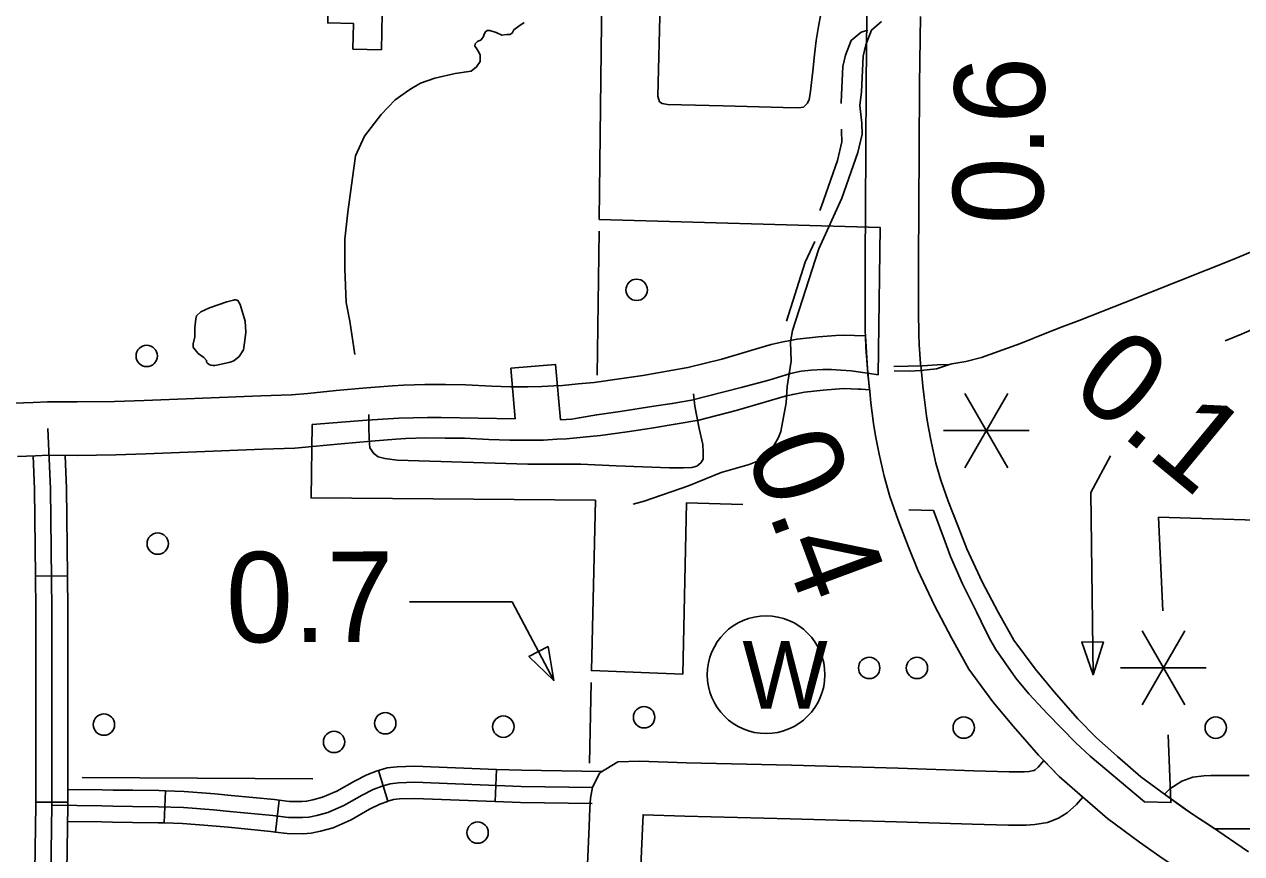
# Model space of a CAD drawing. Extents: x 1382482 to 1385815, y 1168351 to 1170484.
# Drawn here: x 1384167.8 to 1384395.6, y 1168843.1 to 1168998.2 of the extents above; entities that cross this region are included whole.
import ezdxf

# ---------------------------------------------------------------- set-up
doc = ezdxf.new("R2010")
doc.units = 0
for name, color, linetype in [('10', 7, 'Continuous'), ('15', 7, 'Continuous'), ('32', 7, 'Continuous'), ('35', 7, 'Continuous'), ('43', 7, 'Continuous'), ('48', 7, 'Continuous'), ('5', 7, 'Continuous'), ('57', 7, 'Continuous'), ('6', 7, 'Continuous'), ('Default', 7, 'Continuous')]:
    doc.layers.add(name, color=color, linetype=linetype)

msp = doc.modelspace()

# ---------------------------------------------------------------- linework, layer by layer
at = {"layer": '10'}
for points in [[(1384165.85, 1168927.3), (1384169.46, 1168927.46), (1384172.14, 1168927.6), (1384177.69, 1168927.55), (1384184.68, 1168927.65), (1384190.21, 1168927.83), (1384199.63, 1168928.21), (1384212.07, 1168928.69), (1384217.83, 1168928.9), (1384220.83, 1168929.15), (1384226.17, 1168929.68), (1384231.85, 1168930.18), (1384236.67, 1168930.58), (1384238.73, 1168930.69), (1384242.74, 1168930.83), (1384246.62, 1168930.8), (1384250.44, 1168930.77), (1384255.21, 1168930.52), (1384258.83, 1168930.37), (1384262.01, 1168930.4), (1384264.62, 1168930.42), (1384266.88, 1168930.54), (1384268.5, 1168930.64), (1384271.43, 1168930.91), (1384274.42, 1168931.21), (1384279.17, 1168931.85), (1384283.52, 1168932.52), (1384291.96, 1168933.96), (1384298.3, 1168935.56), (1384303.74, 1168937.19), (1384307.55, 1168938.27), (1384309.45, 1168938.75), (1384312.37, 1168939.29), (1384316.38, 1168939.71), (1384319.62, 1168939.95), (1384321.06, 1168940.05), (1384325.16, 1168939.9), (1384325.53, 1168933.74), (1384325.95, 1168929.84)], [(1384325.95, 1168929.84), (1384324.34, 1168929.92), (1384323.81, 1168929.94), (1384321.22, 1168930.04), (1384320.34, 1168929.98), (1384317.28, 1168929.75), (1384313.79, 1168929.38), (1384311.57, 1168928.97), (1384310.13, 1168928.61), (1384306.54, 1168927.59), (1384300.96, 1168925.92), (1384294.02, 1168924.17), (1384285.12, 1168922.65), (1384280.6, 1168921.96), (1384275.59, 1168921.28), (1384272.39, 1168920.96), (1384269.26, 1168920.67), (1384267.46, 1168920.56), (1384264.95, 1168920.42), (1384262.1, 1168920.4), (1384258.67, 1168920.37), (1384254.73, 1168920.53), (1384250.14, 1168920.78), (1384246.55, 1168920.8), (1384242.88, 1168920.83), (1384239.17, 1168920.7), (1384237.35, 1168920.6), (1384232.7, 1168920.22), (1384227.1, 1168919.72), (1384221.73, 1168919.2), (1384218.43, 1168918.92), (1384212.45, 1168918.69), (1384200.02, 1168918.22), (1384190.58, 1168917.84), (1384184.92, 1168917.65), (1384177.72, 1168917.55), (1384172.35, 1168917.6), (1384169.94, 1168917.47), (1384166.56, 1168917.32)], [(1384365.82, 1168853.64), (1384361.43, 1168857.53), (1384358.53, 1168860.52), (1384357.47, 1168859.25), (1384356.91, 1168858.76), (1384356.74, 1168858.65), (1384356.6, 1168858.6), (1384355.77, 1168858.47), (1384354.85, 1168858.4), (1384352.05, 1168858.4), (1384345.44, 1168858.59), (1384331.3, 1168859.04), (1384311.32, 1168859.6), (1384291.69, 1168860.08), (1384282.92, 1168860.37), (1384278.87, 1168860.22), (1384275.5, 1168858.19), (1384274.11, 1168855.53), (1384273.75, 1168853.47), (1384273.63, 1168851.61), (1384273.48, 1168848.22), (1384272.96, 1168836.83)], [(1384390.53, 1168847.69), (1384386.36, 1168850.44), (1384381.11, 1168854.22), (1384382.09, 1168855.22), (1384384.34, 1168856.66), (1384386.41, 1168857.37), (1384388.49, 1168857.65), (1384389.8, 1168857.69), (1384393.21, 1168857.69), (1384396.93, 1168857.69)], [(1384280.65, 1168783.46), (1384280.8, 1168787.57), (1384282.14, 1168814.84), (1384282.95, 1168836.41), (1384283.47, 1168847.78), (1384283.58, 1168850.34), (1384291.4, 1168850.08), (1384311.06, 1168849.6), (1384331, 1168849.04), (1384345.14, 1168848.6), (1384351.91, 1168848.4), (1384355.22, 1168848.4), (1384356.89, 1168848.53), (1384359.21, 1168848.88), (1384361.27, 1168849.69), (1384362.91, 1168850.72), (1384364.65, 1168852.24), (1384365.82, 1168853.64)], [(1384397.11, 1168847.69), (1384393.21, 1168847.69), (1384390.53, 1168847.69)]]:
    msp.add_lwpolyline(points, dxfattribs=at)
at = {"layer": '15'}
for points in [[(1384331.32, 1168905.43), (1384329.76, 1168909.85), (1384328.65, 1168913.64), (1384327.74, 1168917.81), (1384327.06, 1168921.21), (1384326.68, 1168923.5), (1384326.19, 1168927.36), (1384325.98, 1168929.52), (1384325.64, 1168932.77), (1384325.53, 1168933.74), (1384325.24, 1168937.76), (1384325.18, 1168939.82), (1384325.15, 1168940.73), (1384325.1, 1168943.59), (1384325.1, 1168953.72), (1384325.25, 1168974.6), (1384325.28, 1168987.04), (1384325.44, 1168999.69)], [(1384335.44, 1168999.6), (1384335.28, 1168986.96), (1384335.25, 1168974.55), (1384335.1, 1168953.69), (1384335.1, 1168943.67), (1384335.14, 1168940.99), (1384335.17, 1168940.16), (1384335.23, 1168938.27), (1384335.49, 1168934.67), (1384335.58, 1168933.87), (1384335.93, 1168930.53), (1384336.13, 1168928.47), (1384336.58, 1168924.96), (1384336.9, 1168923.01), (1384337.53, 1168919.85), (1384338.35, 1168916.11), (1384339.28, 1168912.92), (1384340.65, 1168909.02)], [(1384340.65, 1168909.02), (1384342.5, 1168904.23), (1384344.16, 1168900.06), (1384347.02, 1168893.93), (1384350.02, 1168888.23), (1384352.96, 1168883.01), (1384356.9, 1168877.63), (1384360.46, 1168873.35), (1384364.91, 1168868.3), (1384368.34, 1168864.77), (1384372.35, 1168861.22), (1384376.68, 1168857.47), (1384382.31, 1168853.34), (1384385, 1168851.42), (1384386.36, 1168850.44), (1384389.88, 1168848.14), (1384396.81, 1168843.43)], [(1384521.35, 1168747.9), (1384489.62, 1168768.93), (1384471.27, 1168781.28), (1384459.46, 1168789.26), (1384446.89, 1168797.82), (1384429.71, 1168809.31), (1384403.51, 1168826.99), (1384391.24, 1168835.12), (1384384.33, 1168839.82), (1384380.68, 1168842.21), (1384379.17, 1168843.3), (1384376.45, 1168845.24), (1384370.45, 1168849.65), (1384365.76, 1168853.69), (1384361.43, 1168857.53), (1384357.56, 1168861.51), (1384352.86, 1168866.85), (1384349.01, 1168871.47), (1384344.54, 1168877.59), (1384341.24, 1168883.44), (1384338.06, 1168889.49), (1384334.98, 1168896.09), (1384333.19, 1168900.58), (1384331.32, 1168905.43)]]:
    msp.add_lwpolyline(points, dxfattribs=at)
at = {"layer": '32'}
for p, q in [((1384255.89, 1168852.85), (1384256.12, 1168858.84)), ((1384235.83, 1168852.88), (1384234.09, 1168858.62)), ((1384193.97, 1168848.82), (1384194.2, 1168854.82)), ((1384214.78, 1168847.11), (1384215.48, 1168853.07))]:
    msp.add_line(p, q, dxfattribs=at)
for points in [[(1384234.09, 1168858.62), (1384235.67, 1168859.1), (1384237.57, 1168859.31), (1384240.84, 1168859.43), (1384256.12, 1168858.84)], [(1384256.12, 1168858.84), (1384260.83, 1168858.66), (1384275.86, 1168858.41)], [(1384215.48, 1168853.07), (1384217.4, 1168852.85), (1384219.78, 1168852.81), (1384220.63, 1168852.88), (1384221.81, 1168853.13), (1384223.62, 1168853.61), (1384226.26, 1168854.76), (1384229.57, 1168856.65), (1384231.9, 1168857.83), (1384233.84, 1168858.54), (1384234.09, 1168858.62)], [(1384172.97, 1168852.13), (1384182.31, 1168852.02), (1384184.35, 1168851.95), (1384188.07, 1168851.92), (1384192.93, 1168851.86), (1384197.59, 1168851.69), (1384203.22, 1168851.3), (1384206.24, 1168850.99), (1384214.28, 1168850.19), (1384217.21, 1168849.85), (1384219.87, 1168849.81), (1384221.06, 1168849.9), (1384222.51, 1168850.21), (1384224.61, 1168850.76), (1384227.61, 1168852.07), (1384231, 1168854.01), (1384233.1, 1168855.08), (1384234.79, 1168855.7), (1384236.27, 1168856.15), (1384237.79, 1168856.32), (1384240.83, 1168856.42), (1384260.75, 1168855.66), (1384274.09, 1168855.44)], [(1384175.97, 1168855.09), (1384182.37, 1168855.02), (1384184.42, 1168854.95), (1384188.1, 1168854.92), (1384193, 1168854.86), (1384194.2, 1168854.82)], [(1384194.2, 1168854.82), (1384197.75, 1168854.69), (1384203.47, 1168854.29), (1384206.54, 1168853.97), (1384214.6, 1168853.18), (1384215.48, 1168853.07)], [(1384214.78, 1168847.11), (1384217.01, 1168846.85), (1384219.96, 1168846.81), (1384221.48, 1168846.92), (1384223.2, 1168847.29), (1384225.6, 1168847.92), (1384228.96, 1168849.39), (1384232.42, 1168851.37), (1384234.3, 1168852.32), (1384235.74, 1168852.85), (1384235.83, 1168852.88)], [(1384235.83, 1168852.88), (1384236.88, 1168853.2), (1384238.01, 1168853.33), (1384240.82, 1168853.42), (1384255.89, 1168852.85)], [(1384255.89, 1168852.85), (1384260.67, 1168852.66), (1384274.04, 1168852.44)], [(1384175.92, 1168849.09), (1384182.24, 1168849.02), (1384184.29, 1168848.95), (1384188.04, 1168848.92), (1384192.86, 1168848.86), (1384193.97, 1168848.82)], [(1384193.97, 1168848.82), (1384197.43, 1168848.7), (1384202.96, 1168848.31), (1384205.94, 1168848), (1384213.95, 1168847.21), (1384214.78, 1168847.11)]]:
    msp.add_lwpolyline(points, dxfattribs=at)
at = {"layer": '35'}
for points in [[(1384261.3, 1168998.51), (1384260.32, 1168997.85), (1384259.42, 1168997.15), (1384259.07, 1168996.52), (1384258.64, 1168996.29), (1384258.09, 1168996.25), (1384257.12, 1168996.13), (1384256.06, 1168996.64), (1384254.93, 1168997.03), (1384254.42, 1168997.03), (1384254.07, 1168996.79), (1384253.82, 1168996.34), (1384253.7, 1168995.88), (1384253.27, 1168995.29), (1384252.6, 1168994.94), (1384252.14, 1168994.51), (1384252.1, 1168994.08), (1384252.33, 1168993.77), (1384252.72, 1168993.14), (1384253.11, 1168992.48)], [(1384253.11, 1168992.48), (1384253.11, 1168991.23), (1384252.41, 1168990.21), (1384251.39, 1168989.43), (1384248.42, 1168988.96), (1384244.59, 1168988.1), (1384241.94, 1168987.16), (1384239.92, 1168985.99), (1384237.22, 1168984.05), (1384234.59, 1168981.3), (1384231.47, 1168977.24), (1384229.75, 1168973.56), (1384228.32, 1168963.02), (1384227.79, 1168958.01), (1384227.76, 1168952.46), (1384228.03, 1168946.16), (1384228.73, 1168942.65), (1384229.28, 1168938.9), (1384229.63, 1168936.39)], [(1384202.43, 1168945.17), (1384205.68, 1168946.27), (1384206.97, 1168946.58), (1384207.16, 1168946.62), (1384207.4, 1168946.62), (1384207.79, 1168946.5), (1384208.18, 1168945.76), (1384209.12, 1168942.63), (1384209.23, 1168940.6), (1384209.04, 1168939.04), (1384208.84, 1168937.28), (1384208.02, 1168936.07), (1384207.01, 1168935.25), (1384206.3, 1168935.01)], [(1384206.3, 1168935.01), (1384204.39, 1168934.54), (1384203.45, 1168934.39), (1384203.1, 1168934.39), (1384202.71, 1168934.42), (1384202.4, 1168934.54), (1384202.08, 1168934.78), (1384201.93, 1168935.01), (1384201.93, 1168935.32), (1384201.38, 1168935.83), (1384200.32, 1168936.61), (1384199.5, 1168937.59), (1384199.43, 1168937.82), (1384199.43, 1168938.41), (1384199.7, 1168939.7), (1384199.74, 1168941.42), (1384199.93, 1168943.06), (1384200.05, 1168943.65), (1384200.87, 1168944.39), (1384202.43, 1168945.17)]]:
    msp.add_lwpolyline(points, dxfattribs=at)
at = {"layer": '43'}
for points in [[(1384281.72, 1168908.46), (1384283.79, 1168909), (1384292.1, 1168911.85), (1384298.18, 1168914.38), (1384303.44, 1168915.85), (1384304.95, 1168916.5), (1384306.53, 1168917.51), (1384307.6, 1168918.64), (1384308.87, 1168920.77), (1384309.34, 1168922.01), (1384310.34, 1168927.38), (1384310.52, 1168930.42), (1384311.29, 1168935.18), (1384311.14, 1168938.82), (1384311.53, 1168940.9), (1384316.46, 1168956.21), (1384320.78, 1168965.63), (1384323.76, 1168974.21), (1384324.53, 1168977.65), (1384324.52, 1168979.69), (1384324.1, 1168982.97), (1384324.44, 1168985.57), (1384324.72, 1168992.21), (1384325.22, 1168994.33), (1384326.28, 1168997.1), (1384328.15, 1168998.67)], [(1384320.61, 1168983.33), (1384320.65, 1168983.61), (1384320.92, 1168990.25), (1384321.43, 1168992.37), (1384322.49, 1168995.14), (1384324.35, 1168996.71), (1384325.64, 1168997.05)], [(1384316.64, 1168963.38), (1384316.98, 1168964.14), (1384319.96, 1168972.71), (1384320.74, 1168976.16), (1384320.72, 1168978.2), (1384320.68, 1168978.56)], [(1384310.38, 1168942.65), (1384313.92, 1168953.67), (1384315.7, 1168957.55)]]:
    msp.add_lwpolyline(points, dxfattribs=at)
at = {"layer": '48'}
for p, q in [((1384351.79, 1168929.1), (1384343.79, 1168915.25)), ((1384343.79, 1168929.1), (1384351.79, 1168915.25)), ((1384339.79, 1168922.18), (1384355.79, 1168922.18)), ((1384384.91, 1168884.77), (1384376.91, 1168870.91)), ((1384376.91, 1168884.77), (1384384.91, 1168870.91)), ((1384372.91, 1168877.84), (1384388.91, 1168877.84))]:
    msp.add_line(p, q, dxfattribs=at)
for points in [[(1384370.99, 1168917.5), (1384367.31, 1168910.6), (1384367.77, 1168876.54)], [(1384239.86, 1168890.2), (1384259.07, 1168890.2), (1384266.89, 1168875.47)]]:
    msp.add_lwpolyline(points, dxfattribs=at)
for points in [[(1384265.82, 1168881.83), (1384262.22, 1168879.92), (1384266.89, 1168875.47)], [(1384369.73, 1168882.69), (1384365.65, 1168882.63), (1384367.77, 1168876.54)]]:
    msp.add_lwpolyline(points, close=True, dxfattribs=at)
at = {"layer": '5'}
for points in [[(1384275.34, 1168959.5), (1384275.01, 1168932.53)], [(1384273.87, 1168875.08), (1384273.52, 1168859.99)], [(1384221.77, 1168857.04), (1384178.65, 1168857.32)]]:
    msp.add_lwpolyline(points, dxfattribs=at)
at = {"layer": '57'}
msp.add_circle((1384306.58, 1168876.54), 11, dxfattribs=at)
at = {"layer": '6'}
for points in [[(1384277.46, 1169131.54), (1384277.31, 1169119.18), (1384276.65, 1169066.63), (1384276.62, 1169064.34), (1384285.92, 1169064.17), (1384285.79, 1169056.4), (1384276.53, 1169056.64), (1384276.01, 1169014.15), (1384275.37, 1168961.67), (1384327.95, 1168960.15), (1384327.52, 1168932.59)], [(1384259.67, 1168924.41), (1384258.84, 1168933.85), (1384267.21, 1168934.58), (1384268.12, 1168924.21)], [(1384327.52, 1168932.59), (1384325.97, 1168932.85), (1384322.52, 1168933.36), (1384320.58, 1168933.47), (1384318.79, 1168933.59), (1384317.17, 1168933.59), (1384315, 1168933.47), (1384313.13, 1168933.28), (1384311.12, 1168932.85), (1384307.09, 1168931.61), (1384301.93, 1168930.25), (1384292.63, 1168927.89), (1384289.02, 1168927.23), (1384285.57, 1168926.76), (1384279.29, 1168925.75), (1384274.92, 1168925.15), (1384271.62, 1168924.56), (1384270.25, 1168924.33), (1384268.12, 1168924.21)], [(1384274.66, 1168909.18), (1384221.45, 1168909.61), (1384221.66, 1168923.35)], [(1384259.67, 1168924.41), (1384245.8, 1168924.63), (1384243.24, 1168924.63), (1384237.85, 1168924.51), (1384231.92, 1168924.12), (1384221.66, 1168923.35)], [(1384291.72, 1168908.66), (1384290.99, 1168876.67), (1384273.92, 1168877.31), (1384274.66, 1168909.18)], [(1384302.21, 1168908.34), (1384291.72, 1168908.66)], [(1384337.88, 1168907.26), (1384333.3, 1168907.4)], [(1384337.88, 1168907.26), (1384340.07, 1168901.36), (1384341.11, 1168898.66), (1384343.35, 1168893.52), (1384345.97, 1168888.32), (1384346.82, 1168886.52), (1384348.38, 1168883.32), (1384349.55, 1168881.24), (1384353.28, 1168875.9), (1384355.72, 1168872.98), (1384359.23, 1168869.23), (1384364.5, 1168863.82), (1384367.23, 1168861.31), (1384377.38, 1168852.76)], [(1384430.64, 1168904.44), (1384380.02, 1168905.98), (1384380.78, 1168888.51)], [(1384381.78, 1168865.28), (1384382.32, 1168852.64), (1384377.38, 1168852.76)]]:
    msp.add_lwpolyline(points, dxfattribs=at)
at = {"layer": 'Default'}
for p, q in [((1384169.89, 1168894.94), (1384175.89, 1168895.01)), ((1384175.97, 1168852.73), (1384169.97, 1168852.73))]:
    msp.add_line(p, q, dxfattribs=at)
msp.add_lwpolyline([(1384234.85, 1169003.57), (1384224.69, 1169003.79), (1384224.57, 1168998.43), (1384229.38, 1168998.33), (1384229.28, 1168993.53), (1384234.63, 1168993.42)], close=True, dxfattribs=at)
for points in [[(1384286.76, 1169002.09), (1384286.34, 1168984.72), (1384286.62, 1168983.7), (1384287.13, 1168983.33), (1384288.15, 1168983.19), (1384290.75, 1168983.09), (1384298.57, 1168982.9)], [(1384298.57, 1168982.9), (1384309.79, 1168982.59), (1384312.67, 1168982.54), (1384313.59, 1168982.68), (1384314.34, 1168983.43), (1384314.66, 1168984.12), (1384314.8, 1168985.15), (1384315.36, 1168989.42), (1384315.64, 1168992.49), (1384315.96, 1168995.13), (1384316.38, 1168997.78), (1384316.84, 1169000.1)], [(1384407.45, 1168959.71), (1384406.97, 1168949.33), (1384406.78, 1168947.52), (1384406.63, 1168946.68), (1384406.36, 1168946), (1384405.94, 1168945.29), (1384405.29, 1168944.68), (1384404.29, 1168944), (1384402.14, 1168942.95), (1384397.94, 1168941.3), (1384395.55, 1168940.25), (1384392.48, 1168938.99)], [(1384403.65, 1168958.25), (1384393.79, 1168954.12), (1384373.68, 1168946.15), (1384365.18, 1168942.78), (1384361.97, 1168941.58), (1384359.13, 1168940.48), (1384354.18, 1168938.47), (1384350.89, 1168937.32), (1384346.86, 1168935.85), (1384343.97, 1168935.12), (1384341.31, 1168934.66), (1384340.87, 1168934.57)], [(1384340.87, 1168934.57), (1384338.56, 1168934.47), (1384335.84, 1168934.29), (1384330.51, 1168934.2)], [(1384330.54, 1168933.35), (1384333.43, 1168933.32), (1384335.56, 1168933.44), (1384338.44, 1168933.75), (1384339.76, 1168934.16), (1384340.87, 1168934.57)], [(1384292.99, 1168929.07), (1384293.28, 1168926.77), (1384294.09, 1168922.61), (1384294.76, 1168919.6), (1384294.81, 1168918.07), (1384294.81, 1168916.87), (1384294.38, 1168916.16), (1384293.61, 1168915.54), (1384292.7, 1168915.3), (1384291.13, 1168915.2), (1384288.5, 1168915.25), (1384278.55, 1168915.63), (1384271.91, 1168915.92), (1384262.03, 1168915.92), (1384237.59, 1168916.68), (1384235.29, 1168916.97), (1384234, 1168917.31), (1384233.19, 1168917.88), (1384232.47, 1168918.98), (1384232.42, 1168919.74), (1384232.28, 1168922.47), (1384232.27, 1168925.2)], [(1384166.76, 1168702.36), (1384167.86, 1168703.6), (1384168.73, 1168704.94), (1384169.35, 1168706.36), (1384169.87, 1168707.74), (1384170.24, 1168710.26), (1384170.35, 1168712.16), (1384170.76, 1168732.56), (1384172.28, 1168804.42), (1384172.97, 1168852.13), (1384172.97, 1168888.73), (1384172.69, 1168911.31), (1384172.24, 1168922.6)], [(1384169.89, 1168894.94), (1384169.7, 1168911.23), (1384169.45, 1168917.45)], [(1384175.89, 1168895.01), (1384175.69, 1168911.38), (1384175.45, 1168917.51)], [(1384169.97, 1168873.85), (1384169.97, 1168888.71), (1384169.89, 1168894.94)], [(1384175.89, 1168895.01), (1384175.97, 1168888.75), (1384175.97, 1168873.85)], [(1384169.97, 1168852.73), (1384169.97, 1168873.85)], [(1384175.97, 1168873.85), (1384175.97, 1168852.73)], [(1384169.67, 1168831.66), (1384169.97, 1168852.15), (1384169.97, 1168852.73)], [(1384175.67, 1168831.57), (1384175.97, 1168852.1), (1384175.97, 1168852.73)]]:
    msp.add_lwpolyline(points, dxfattribs=at)
for centre in [(1384282.37, 1168948.51), (1384190.72, 1168936.15), (1384192.78, 1168901.06), (1384325.87, 1168877.81), (1384334.81, 1168877.81), (1384283.77, 1168868.58), (1384182.7, 1168867.21), (1384235.35, 1168867.47), (1384257.43, 1168866.82), (1384343.57, 1168866.66), (1384390.71, 1168866.64), (1384225.76, 1168863.97), (1384252.61, 1168847.01)]:
    msp.add_circle(centre, 2, dxfattribs=at)

# ---------------------------------------------------------------- texts
at = {"layer": '48'}
for s, rotation, p in [('0.6', 89.2034, (1384358.35, 1168960.62)), ('0.1', 320.4978, (1384362.97, 1168929.5)), ('0.4', 290.3763, (1384302.58, 1168918.65)), ('0.7', 0.2353, (1384205.55, 1168882.58))]:
    msp.add_text(s, height=16.896, rotation=rotation, dxfattribs=at).set_placement(p)
at = {"layer": '57'}
msp.add_text('W', height=12.67, dxfattribs=at).set_placement((1384302.14, 1168870.2))

doc.saveas('drawing.dxf')
